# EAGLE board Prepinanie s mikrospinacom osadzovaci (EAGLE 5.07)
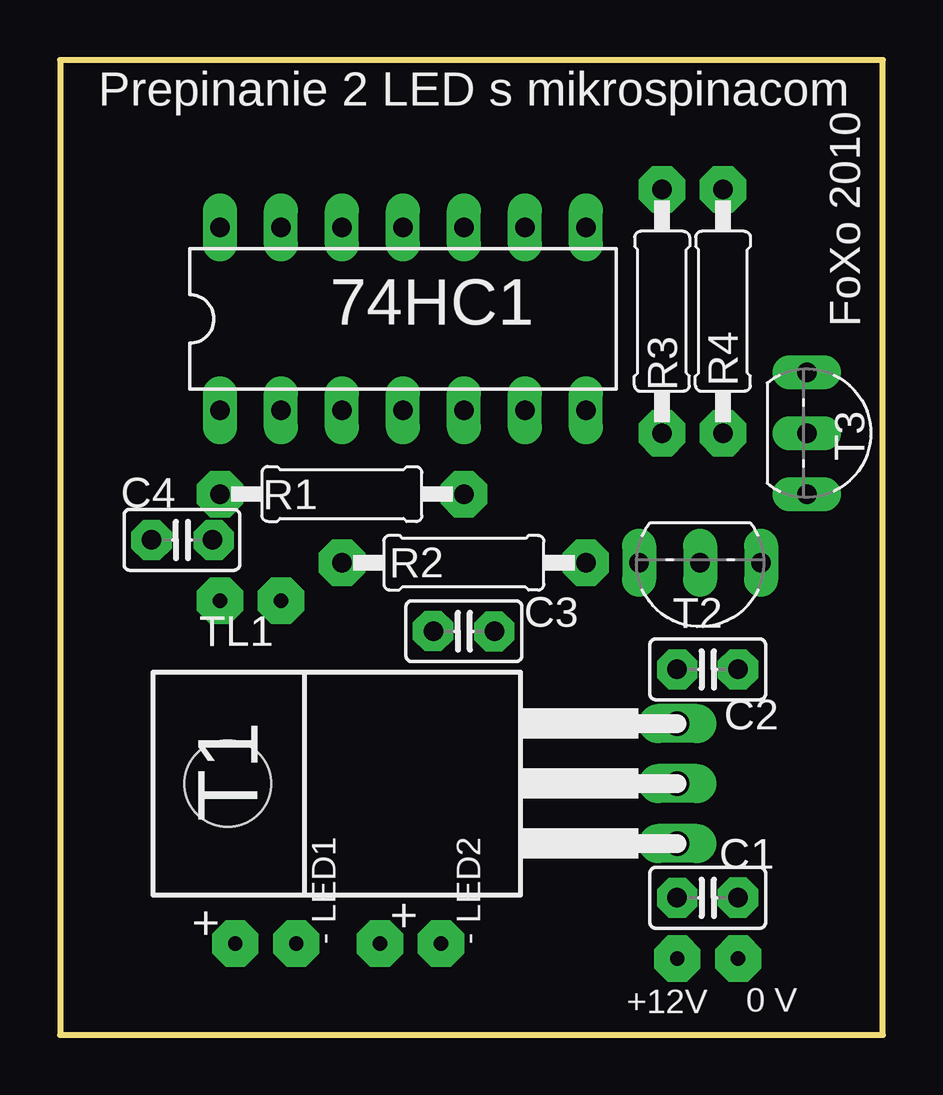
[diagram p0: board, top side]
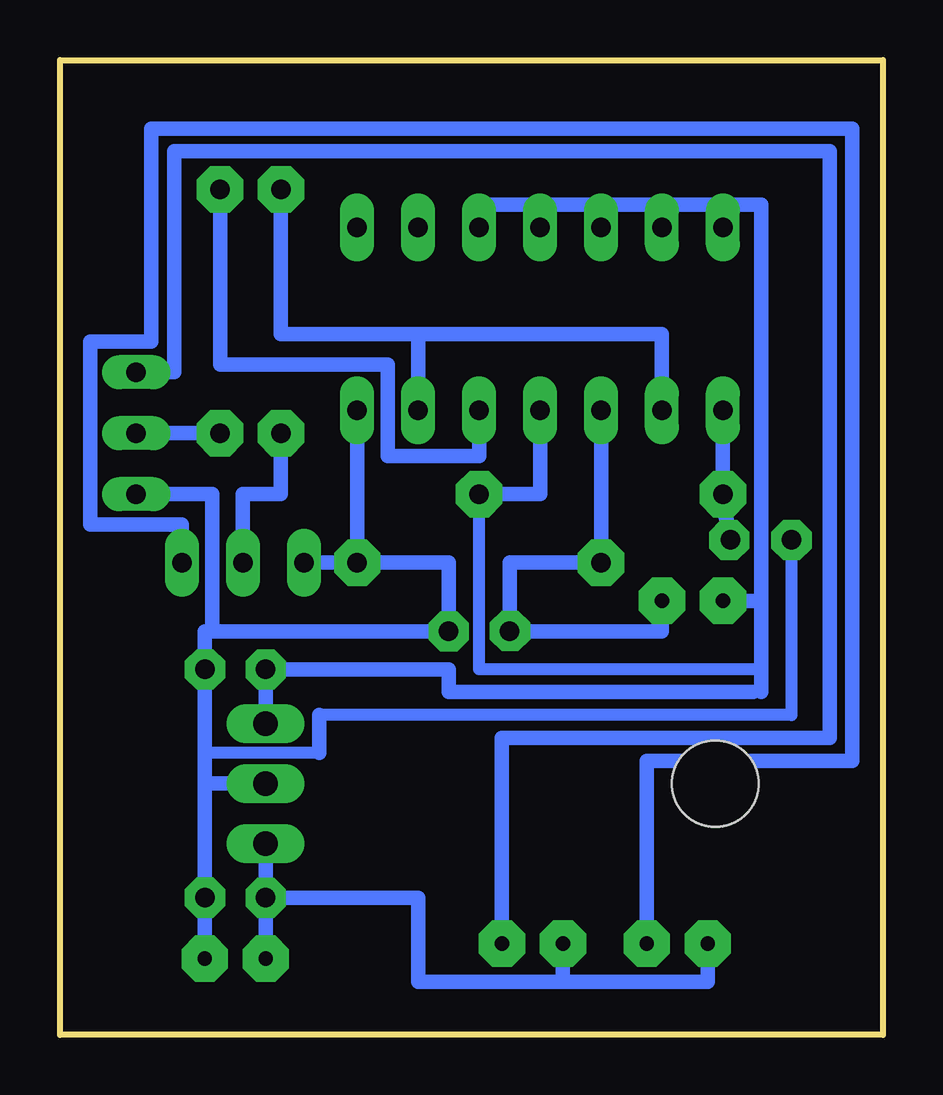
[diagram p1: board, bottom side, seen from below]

Size 34.29 x 40.64 mm. Coordinates in mm from the lower left corner, seen from the top.
Outline: 34.29,40.64 0,40.64 0,0 34.29,0 34.29,40.64
Copper layers (1*16): Top 0.035mm / dielectric 1.5mm / Bottom 0.035mm
Design rules "default *": minimum track width 10mil, minimum drill 24mil, track to track 8mil, track to pad 8mil, pad to pad 8mil, via to via 8mil, smd to smd 8mil, copper to edge 40mil, drill to drill 8mil, minimum pad ring 12mil, minimum via ring 8mil, stop-mask expansion 4mil, vias tented up to drill 0mil, thermal gap 10mil

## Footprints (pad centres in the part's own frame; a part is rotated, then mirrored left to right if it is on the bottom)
DIL14 = drill 0.813 long: 1 -7.62,-3.81; 2 -5.08,-3.81; 3 -2.54,-3.81; 4 0,-3.81; 5 2.54,-3.81; 6 5.08,-3.81; 7 7.62,-3.81; 8 7.62,3.81; 9 5.08,3.81; 10 2.54,3.81; 11 0,3.81; 12 -2.54,3.81; 13 -5.08,3.81; 14 -7.62,3.81
C025-025X050 = drill 0.813 octagon: 1 -1.27,0; 2 1.27,0
R-10 = drill 0.813 pad 1.93 octagon: 1 -5.08,0; 2 5.08,0
T-30 = drill 1.016 long: 1 -2.5,-18.735; 2 0,-18.735; 3 2.5,-18.735 | hole 3.6: 0,0
TO92-CBE = drill 0.813 long: B 0,0; C -2.54,0; E 2.54,0

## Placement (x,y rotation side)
74HC1  [DIL14]  14.29,29.84 0 top
C1  [C025-025X050]  26.99,5.71 0 top
C2  [C025-025X050]  26.99,15.24 0 top
C3  [C025-025X050]  16.83,16.83 180 top
C4  [C025-025X050]  5.08,20.64 180 top
R1  [R-10]  11.75,22.54 180 top
R2  [R-10]  16.83,19.69 0 top
R3  [R-10]  25.08,30.16 270 top
R4  [R-10]  27.62,30.16 270 top
T1  [T-30]  6.98,10.48 90 top
T2  [TO92-CBE]  26.67,19.69 180 top
T3  [TO92-CBE]  31.11,25.08 270 top

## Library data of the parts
74HC1 = 74ac-logic
C1-C4 = rcl
R1-R4 = #PaJa_21
T1-T3 = transistor

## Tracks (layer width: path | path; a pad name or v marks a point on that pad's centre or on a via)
S$2
  Bottom 0.61: 30.16,22.54 27.94,22.54 27.94,16.83 | 28.26,15.87 28.26,16.83 27.94,16.83 | 18.73,16.83 27.94,16.83
S$3
  Bottom 0.61: 25.72,4.13 25.72,5.08
S$5  (via drill 0.6 pad 1.68)
  other vias: 27.61,35.25
S$6  (via drill 0.6 pad 1.68)
  other vias: 6.41,20.62
S$7  (via drill 0.6 pad 1.68)
  other vias: 11.74,19.7
S$8  (via drill 0.6 pad 1.68)
  other vias: 18.09,16.81
S$9  (via drill 0.6 pad 1.68)
  other vias: 16.83,22.55
S$11  (via drill 0.6 pad 1.68)
  other vias: 6.65,22.55
S$12  (via drill 0.6 pad 1.68)
  other vias: 3.81,20.62
S$13  (via drill 0.6 pad 1.68)
  other vias: 28.25,15.23
S$14  (via drill 0.6 pad 1.68)
  other vias: 21.89,19.69
S$15  (via drill 0.6 pad 1.68)
  other vias: 28.25,5.72
S$16
  Bottom 0.61: 28.26,5.08 28.26,3.81
S$17  (via drill 0.6 pad 1.68)
  other vias: 25.72,15.23
S$18  (via drill 0.6 pad 1.68)
  other vias: 25.72,5.71
S$19  (via drill 0.6 pad 1.68)
  other vias: 25.07,25.06
S$20  (via drill 0.6 pad 1.68)
  other vias: 27.62,25.07
S$21  (via drill 0.6 pad 1.68)
  other vias: 25.08,35.25
S$22  (via drill 0.6 pad 1.68)
  other vias: 15.54,16.84
S$55  (via drill 0.6 pad 1.93)
  other vias: 6.67,18.1
S$56  (via drill 0.6 pad 1.93)
  other vias: 15.87,3.81
S$57  (via drill 0.6 pad 1.93)
  other vias: 9.84,3.81
S$60  (via drill 0.6 pad 1.93)
  other vias: 9.21,18.1
S$61  (via drill 0.6 pad 1.93)
  other vias: 13.33,3.81 25.72,3.17 28.26,3.17 7.3,3.81
S$62
  Bottom 0.61: 6.67,24.77 6.67,23.18
S$63
  Bottom 0.61: 16.19,22.54 14.29,22.54 14.29,24.77
S$64
  Bottom 0.61: 11.75,24.77 11.75,20.32
S$65
  Bottom 0.61: 21.91,24.77 21.91,20.32
S$66
  Bottom 0.61: 21.27,19.69 18.1,19.69 18.1,17.46
S$67
  Bottom 0.61: 12.38,19.69 15.56,19.69 15.56,17.46
S$68
  Bottom 0.61: 14.92,16.83 9.21,16.83 9.21,17.14
S$69
  Bottom 0.61: 25.72,6.35 25.72,7.3
S$70
  Bottom 0.5: 16.83,21.91 16.83,15.24 5.08,15.24
  Bottom 0.61: 16.83,34.61 5.08,34.61 5.08,18.1 | 5.08,18.1 6.03,18.1 | 5.08,14.29 5.08,15.24 5.08,18.1
S$71
  Bottom 0.61: 6.67,21.91 6.45,21.3
S$72
  Bottom 0.5: 23.5,11.75 28.26,11.75 | 23.5,13.33 3.81,13.33 3.81,20
  Bottom 0.61: 28.26,10.48 28.26,6.35 | 28.26,10.48 26.99,10.48 | 28.26,10.48 28.26,11.75 28.26,14.6 | 23.5,13.33 23.5,11.75
S$73
  Bottom 0.61: 25.72,13.65 25.72,14.6
S$74
  Bottom 0.61: 5.4,14.29 18.1,14.29 18.1,15.24 25.08,15.24
S$76
  Bottom 0.61: 25.08,5.71 19.37,5.71 19.37,4.44
S$77
  Bottom 0.61: 19.37,4.44 19.37,2.22 13.33,2.22 | 13.33,2.22 13.33,2.86 | 13.33,2.22 7.3,2.22 7.3,2.86
S$78
  Bottom 0.61: 25.08,34.61 25.08,29.21 19.37,29.21 | 9.21,27.3 9.21,29.21 19.37,29.21 | 19.37,29.21 19.37,27.3
S$79
  Bottom 0.61: 27.62,34.61 27.62,27.94 20.64,27.94 20.64,24.13 16.83,24.13 16.83,24.77
S$80
  Bottom 0.61: 22.54,19.69 23.5,19.69
S$81
  Bottom 0.61: 25.08,24.45 25.08,22.54 26.67,22.54 26.67,20.64
S$82
  Bottom 0.61: 30.16,25.08 28.26,25.08
S$84
  Bottom 0.61: 15.87,4.44 15.87,12.38 2.22,12.38 2.22,36.83 29.53,36.83 29.53,27.62 30.16,27.62
S$85
  Bottom 0.61: 29.21,20.95 29.21,21.27 33.02,21.27 33.02,28.89 30.48,28.89 30.48,37.78 1.27,37.78 1.27,11.43 9.84,11.43 9.84,4.44

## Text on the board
tNames: Prepinanie 2 LED s mikrospinacom | FoXo 2010 | TL1 | - LED1 | - LED2 | + | + | +12V | 0 V
Doplnky: E | B | C | E | B | C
